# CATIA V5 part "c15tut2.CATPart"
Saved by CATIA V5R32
Part number: Part1
Bounding box of the stored display mesh (mm): x -55 to 55, y -20 to 21, z -12 to 52.853
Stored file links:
  D:\PROJECTS\Project 2022\CATIA V5 6R 2022\Resources\Tutorial Files\c15_catia_v5_6r2022_tut\c15tut2.CATPart
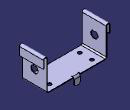
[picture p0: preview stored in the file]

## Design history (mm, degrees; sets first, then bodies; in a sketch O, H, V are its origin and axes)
SheetMetalParameters1: Thickness 1, BendRadius 2, KFactor 0.400515 {= log(min(100,max(20*SheetMetalParameters1.BendRadius,SheetMetalParameters1.Thickness)/SheetMetalParameters1.Thickness))/log(100)/2}, ReliefRadialLength 1, ReliefAxialLength 1, MinimumBendRadius 0
Body1 (main body)
  Sketch1 on xy-plane, origin (0, 0, 0), H (1, 0, 0), V (0, 1, 0)
    line L1 (50, 20) -> (50, -20)
    line L2 (50, -20) -> (-50, -20)
    line L3 (-50, -20) -> (-50, 20)
    line L4 (-50, 20) -> (50, 20)
    length L4 = 100
    length L1 = 40
    vertical: L1 V, L3 V
    horizontal: L2 H, L4 H
    equidistance: L1 L3 O, L2 L4 O
  Wall1: Thickness 1, Profile Sketch1
  Sketch2 on face of Wall1, origin (29.2419, -0.5458, 1), H (1, 0, 0), V (0, 1, 0)
    point P1 (-64.2419, -9.4542)
    reference projected line E1 (-79.2419, -19.4542) -> (-79.2419, 20.5458) from edge [face of Wall1 | face of Wall1]
    reference projected line E2 (20.7581, -19.4542) -> (-79.2419, -19.4542) from edge [face of Wall1 | face of Wall1]
    distance E1 P1 = 15
    distance E2 P1 = 10
  Hole1: placed by Sketch2, at (-35, -10, 1) direction (0, 0, -1), diameter 6, depth 10
  RectPattern1: of Hole1, direction 1 instances 2, spacing 70, along edge [face of Wall1 | face of Wall1] reversed, direction 2 instances 2, spacing 20, along edge [face of Wall1 | face of Wall1]
  Flange1: Angle 90, Length 50, Radius 2, KFacteur 0.400515 {= log(min(100,max(20*Flange1.Radius,SheetMetalParameters1.Thickness)/SheetMetalParameters1.Thickness))/log(100)/2}, Guide edge [face of Wall1 | face of Wall1]
  Flange2: Angle 90, Length 50, Radius 2, KFacteur 0.400515 {= log(min(100,max(20*Flange2.Radius,SheetMetalParameters1.Thickness)/SheetMetalParameters1.Thickness))/log(100)/2}, Guide edge [face of Wall1 | face of Wall1]
  Flange3: Angle 90, Length 13, Radius 2, KFacteur 0.400515 {= log(min(100,max(20*Flange3.Radius,SheetMetalParameters1.Thickness)/SheetMetalParameters1.Thickness))/log(100)/2}, Guide edge [face of Flange2 | face of Flange2]
  Flange4: Angle 90, Length 13, Radius 2, KFacteur 0.400515 {= log(min(100,max(20*Flange4.Radius,SheetMetalParameters1.Thickness)/SheetMetalParameters1.Thickness))/log(100)/2}, Guide edge [face of Flange1 | face of Flange1]
  Sketch3 on face of Flange1, origin (50, 0, 0), H (0, 1, 0), V (0, 0, 1)
    arc A1 centre (0, 25) radius 6 from (-2, 30.6569) to (2, 30.6569) ccw
    point P1 (0, 25)
    line L1 (-2, 30.6569) -> (-2, 29.5)
    point P2 (-2, 29.5)
    line L2 (-2, 29.5) -> (2, 29.5)
    line L3 (2, 29.5) -> (2, 30.6569)
    radius A1 = 6
    distance H P1 = 25
    distance L3 L1 = 4
    distance P2 P1 H = 2
    distance L2 A1 = 10.5
    coincidence: P1 V
    vertical: L1 V, L3 V
    horizontal: L2 H
  CutOut1: Direction Sketch3, EndLimit through (limit type 3), Orientation true, Profile Sketch3, StartLimit through (limit type 2), Thickness1 2, Thickness2 2
  d_NewWallOnEdge1: NewWallOnEdge_Edge edge [face of Wall1 | face of Wall1], NewWallOnEdge_Length 13, NewWallOnEdge_HeightLimitOffset 0, NewWallOnEdge_WidthOffset1 -42, NewWallOnEdge_WidthOffset2 -42, NewWallOnEdge_Angle 90, NewWallOnEdge_BendRadiusValue 2 {= SheetMetalParameters1.BendRadius}, KFacteur 0.400515 {= log(min(100,max(20*d_NewWallOnEdge1.Radius,SheetMetalParameters1.Thickness)/SheetMetalParameters1.Thickness))/log(100)/2}
  Corner1: CornerRadius 3, CornerChamferEdges (edge [face of d_NewWallOnEdge1 | face of d_NewWallOnEdge1]; edge [face of d_NewWallOnEdge1 | face of d_NewWallOnEdge1])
